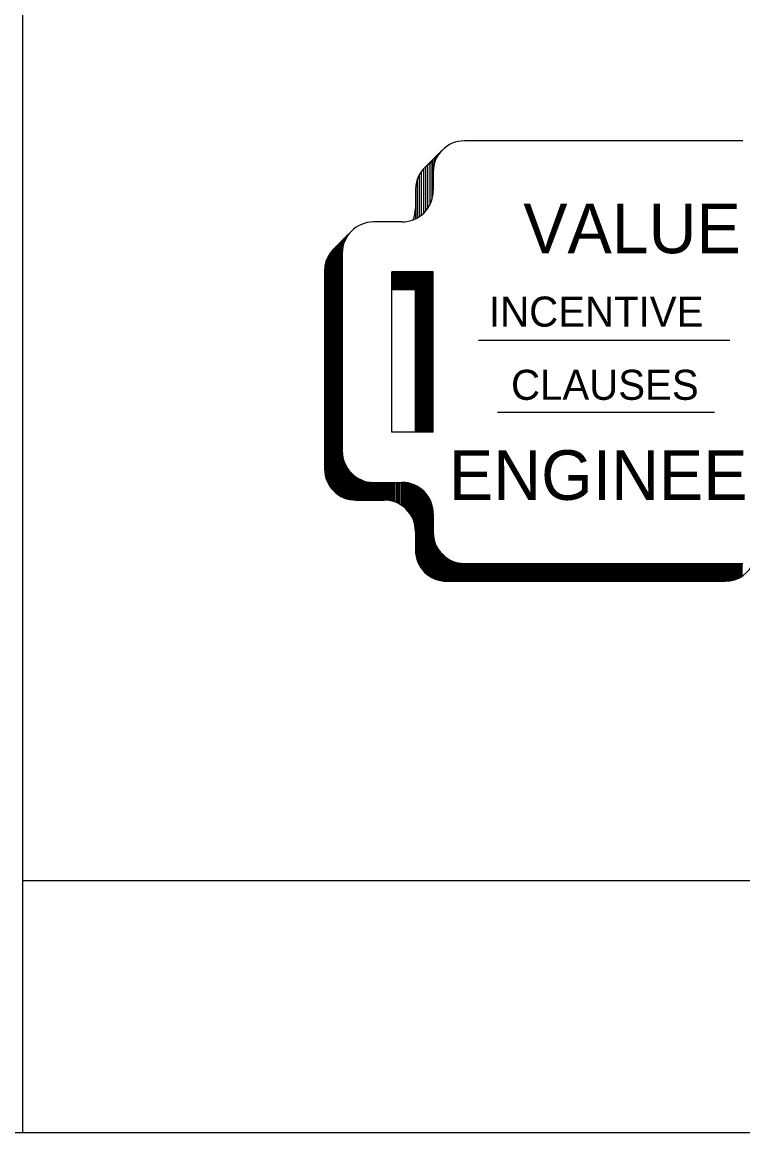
# Model space of a CAD drawing. Extents: x 44743.44 to 44747.1, y 44738.46 to 44741.29.
# Drawn here: x 44743.563 to 44743.6828, y 44738.4578 to 44738.6426 of the extents above; entities that cross this region are included whole.
import ezdxf

# ---------------------------------------------------------------- set-up
doc = ezdxf.new("R2010")
doc.units = 0
for name, color, linetype in [('Level 1', 7, 'Continuous'), ('Level 10', 7, 'Continuous'), ('Level 2', 7, 'Continuous'), ('Level 7', 7, 'Continuous'), ('Level 9', 7, 'Continuous')]:
    doc.layers.add(name, color=color, linetype=linetype)

msp = doc.modelspace()

# ---------------------------------------------------------------- linework, layer by layer
at = {"layer": 'Level 1'}
msp.add_lwpolyline([(44743.43805, 44741.29183), (44747.10474, 44741.29183), (44747.10474, 44738.45783), (44743.43805, 44738.45783)], close=True, dxfattribs=at)
at = {"layer": 'Level 10'}
msp.add_line((44743.56305, 44738.45783), (44743.56305, 44738.49983), dxfattribs=at)
at = {"layer": 'Level 2'}
for p, q in [((44743.62991, 44738.6184), (44743.63286, 44738.62135)), ((44743.63212, 44738.6204), (44743.63212, 44738.62061)), ((44743.63234, 44738.62073), (44743.63234, 44738.62083)), ((44743.6304, 44738.61889), (44743.6304, 44738.61161)), ((44743.63077, 44738.61927), (44743.63077, 44738.61223)), ((44743.63113, 44738.61962), (44743.63113, 44738.61313)), ((44743.63134, 44738.61766), (44743.63134, 44738.61983)), ((44743.63159, 44738.61926), (44743.63159, 44738.62008)), ((44743.63186, 44738.61993), (44743.63186, 44738.62035)), ((44743.62902, 44738.6172), (44743.62902, 44738.61026)), ((44743.62935, 44738.61772), (44743.62935, 44738.6105)), ((44743.6297, 44738.61817), (44743.6297, 44738.6108)), ((44743.63005, 44738.61854), (44743.63005, 44738.61115)), ((44743.62867, 44738.6164), (44743.62867, 44738.61005)), ((44743.62839, 44738.61471), (44743.62839, 44738.6099)), ((44743.61479, 44738.60491), (44743.61773, 44738.60786)), ((44743.61573, 44738.60586), (44743.61573, 44738.56388)), ((44743.61587, 44738.606), (44743.61587, 44738.5638)), ((44743.616, 44738.60613), (44743.616, 44738.56372)), ((44743.6161, 44738.60622), (44743.6161, 44738.56367)), ((44743.61621, 44738.60417), (44743.61621, 44738.60634)), ((44743.61633, 44738.60526), (44743.61633, 44738.60645)), ((44743.61647, 44738.6058), (44743.61647, 44738.6066)), ((44743.61659, 44738.60611), (44743.61659, 44738.60671)), ((44743.61669, 44738.60635), (44743.61669, 44738.60682)), ((44743.61679, 44738.60655), (44743.61679, 44738.60691)), ((44743.61689, 44738.60675), (44743.61689, 44738.60702)), ((44743.61699, 44738.60691), (44743.61699, 44738.60712)), ((44743.6171, 44738.60708), (44743.6171, 44738.60722)), ((44743.6172, 44738.60722), (44743.6172, 44738.60733)), ((44743.61404, 44738.60395), (44743.61404, 44738.56558)), ((44743.6142, 44738.6042), (44743.6142, 44738.56533)), ((44743.61438, 44738.60444), (44743.61438, 44738.56509)), ((44743.61452, 44738.60462), (44743.61452, 44738.56491)), ((44743.61466, 44738.60478), (44743.61466, 44738.56476)), ((44743.61481, 44738.60492), (44743.61481, 44738.56461)), ((44743.61498, 44738.60511), (44743.61498, 44738.56444)), ((44743.61511, 44738.60523), (44743.61511, 44738.56433)), ((44743.61524, 44738.60537), (44743.61524, 44738.56422)), ((44743.61541, 44738.60554), (44743.61541, 44738.5641)), ((44743.61559, 44738.60571), (44743.61559, 44738.56397)), ((44743.61341, 44738.60244), (44743.61341, 44738.56709)), ((44743.61357, 44738.60297), (44743.61357, 44738.56656)), ((44743.61373, 44738.60338), (44743.61373, 44738.56615)), ((44743.61387, 44738.60366), (44743.61387, 44738.56587)), ((44743.61326, 44738.60122), (44743.61326, 44738.56831)), ((44743.63134, 44738.60091), (44743.62444, 44738.60091)), ((44743.63134, 44738.60078), (44743.62444, 44738.60078)), ((44743.63134, 44738.60062), (44743.62444, 44738.60062)), ((44743.63134, 44738.60046), (44743.62444, 44738.60046)), ((44743.63134, 44738.6003), (44743.62444, 44738.6003)), ((44743.63134, 44738.60105), (44743.62839, 44738.5981)), ((44743.63134, 44738.60014), (44743.62444, 44738.60014)), ((44743.63134, 44738.59998), (44743.62444, 44738.59998)), ((44743.63134, 44738.59982), (44743.62444, 44738.59982)), ((44743.63134, 44738.59967), (44743.62444, 44738.59967)), ((44743.63134, 44738.59952), (44743.62444, 44738.59952)), ((44743.63134, 44738.59936), (44743.62444, 44738.59936)), ((44743.63134, 44738.59921), (44743.62444, 44738.59921)), ((44743.63134, 44738.59907), (44743.62444, 44738.59907)), ((44743.63134, 44738.59894), (44743.62444, 44738.59894)), ((44743.63134, 44738.59879), (44743.62444, 44738.59879)), ((44743.63134, 44738.59866), (44743.62444, 44738.59866)), ((44743.63134, 44738.59853), (44743.62444, 44738.59853)), ((44743.63134, 44738.5984), (44743.62444, 44738.5984)), ((44743.63134, 44738.59825), (44743.62444, 44738.59825)), ((44743.62839, 44738.5981), (44743.62444, 44738.5981)), ((44743.62839, 44738.57438), (44743.62839, 44738.5981)), ((44743.62854, 44738.57438), (44743.62854, 44738.59825)), ((44743.62865, 44738.57438), (44743.62865, 44738.59825)), ((44743.62877, 44738.57438), (44743.62877, 44738.59825)), ((44743.62888, 44738.57438), (44743.62888, 44738.59825)), ((44743.62904, 44738.57438), (44743.62904, 44738.59825)), ((44743.62917, 44738.57438), (44743.62917, 44738.59825)), ((44743.62932, 44738.57438), (44743.62932, 44738.59825)), ((44743.62942, 44738.57438), (44743.62942, 44738.59825)), ((44743.62959, 44738.57438), (44743.62959, 44738.59825)), ((44743.62972, 44738.57438), (44743.62972, 44738.59825)), ((44743.62984, 44738.57438), (44743.62984, 44738.59825)), ((44743.62997, 44738.57438), (44743.62997, 44738.59825)), ((44743.63011, 44738.57438), (44743.63011, 44738.59825)), ((44743.63026, 44738.57438), (44743.63026, 44738.59825)), ((44743.63039, 44738.57438), (44743.63039, 44738.59825)), ((44743.63051, 44738.57438), (44743.63051, 44738.59825)), ((44743.63067, 44738.57438), (44743.63067, 44738.59825)), ((44743.63083, 44738.57438), (44743.63083, 44738.59825)), ((44743.63098, 44738.57438), (44743.63098, 44738.59825)), ((44743.63109, 44738.57438), (44743.63109, 44738.59825)), ((44743.63122, 44738.57438), (44743.63122, 44738.59825)), ((44743.61629, 44738.57039), (44743.61629, 44738.56358)), ((44743.61645, 44738.56969), (44743.61645, 44738.56351)), ((44743.61661, 44738.56927), (44743.61661, 44738.56344)), ((44743.61676, 44738.56892), (44743.61676, 44738.56339)), ((44743.61695, 44738.56858), (44743.61695, 44738.56333)), ((44743.61709, 44738.56837), (44743.61709, 44738.56329)), ((44743.61722, 44738.56817), (44743.61722, 44738.56326)), ((44743.6174, 44738.56794), (44743.6174, 44738.56321)), ((44743.61755, 44738.56778), (44743.61755, 44738.56318)), ((44743.6177, 44738.56761), (44743.6177, 44738.56316)), ((44743.61786, 44738.56745), (44743.61786, 44738.56313)), ((44743.61801, 44738.56732), (44743.61801, 44738.56312)), ((44743.61816, 44738.56719), (44743.61816, 44738.56311)), ((44743.61834, 44738.56706), (44743.61834, 44738.5631)), ((44743.61849, 44738.56694), (44743.61849, 44738.5631)), ((44743.61865, 44738.56685), (44743.61865, 44738.5631)), ((44743.61881, 44738.56676), (44743.61881, 44738.5631)), ((44743.61899, 44738.56665), (44743.61899, 44738.5631)), ((44743.61913, 44738.56658), (44743.61913, 44738.5631)), ((44743.61921, 44738.56654), (44743.61921, 44738.5631)), ((44743.61935, 44738.56647), (44743.61935, 44738.5631)), ((44743.61948, 44738.56642), (44743.61948, 44738.5631)), ((44743.61965, 44738.56636), (44743.61965, 44738.5631)), ((44743.61982, 44738.5663), (44743.61982, 44738.5631)), ((44743.61997, 44738.56626), (44743.61997, 44738.5631)), ((44743.62018, 44738.56619), (44743.62018, 44738.5631)), ((44743.62037, 44738.56615), (44743.62037, 44738.5631)), ((44743.62052, 44738.56612), (44743.62052, 44738.5631)), ((44743.62064, 44738.56611), (44743.62064, 44738.5631)), ((44743.6208, 44738.56609), (44743.6208, 44738.5631)), ((44743.62093, 44738.56607), (44743.62093, 44738.5631)), ((44743.62105, 44738.56606), (44743.62105, 44738.5631)), ((44743.62119, 44738.56605), (44743.62119, 44738.5631)), ((44743.62136, 44738.56605), (44743.62136, 44738.5631)), ((44743.62151, 44738.56605), (44743.62151, 44738.5631)), ((44743.62169, 44738.56605), (44743.62169, 44738.5631)), ((44743.62187, 44738.56605), (44743.62187, 44738.5631)), ((44743.62202, 44738.56605), (44743.62202, 44738.5631)), ((44743.62223, 44738.56605), (44743.62223, 44738.5631)), ((44743.62241, 44738.56605), (44743.62241, 44738.5631)), ((44743.62257, 44738.56605), (44743.62257, 44738.5631)), ((44743.62274, 44738.56605), (44743.62274, 44738.5631)), ((44743.62294, 44738.56605), (44743.62294, 44738.5631)), ((44743.62313, 44738.56605), (44743.62313, 44738.5631)), ((44743.62333, 44738.56605), (44743.62333, 44738.5631)), ((44743.62352, 44738.56605), (44743.62352, 44738.5631)), ((44743.62375, 44738.56605), (44743.62375, 44738.56307)), ((44743.62391, 44738.56605), (44743.62391, 44738.56305)), ((44743.62405, 44738.56605), (44743.62405, 44738.56303)), ((44743.62418, 44738.56605), (44743.62418, 44738.56301)), ((44743.6244, 44738.56605), (44743.6244, 44738.56295)), ((44743.62463, 44738.56605), (44743.62463, 44738.56289)), ((44743.62487, 44738.56605), (44743.62487, 44738.56282)), ((44743.6251, 44738.56605), (44743.6251, 44738.56273)), ((44743.6253, 44738.56605), (44743.6253, 44738.56265)), ((44743.62552, 44738.56605), (44743.62552, 44738.56255)), ((44743.6257, 44738.56605), (44743.6257, 44738.56245)), ((44743.62597, 44738.56605), (44743.62597, 44738.56229)), ((44743.62619, 44738.56605), (44743.62619, 44738.56214)), ((44743.62631, 44738.56605), (44743.62631, 44738.56206)), ((44743.6265, 44738.56605), (44743.6265, 44738.5619)), ((44743.62666, 44738.56602), (44743.62666, 44738.56177)), ((44743.62683, 44738.566), (44743.62683, 44738.56161)), ((44743.62698, 44738.56597), (44743.62698, 44738.56145)), ((44743.6271, 44738.56595), (44743.6271, 44738.56133)), ((44743.62727, 44738.56592), (44743.62727, 44738.56111)), ((44743.62745, 44738.56588), (44743.62745, 44738.56087)), ((44743.62764, 44738.56583), (44743.62764, 44738.56058)), ((44743.62782, 44738.56577), (44743.62782, 44738.56027)), ((44743.62797, 44738.56571), (44743.62797, 44738.55993)), ((44743.62814, 44738.56564), (44743.62814, 44738.55948)), ((44743.62832, 44738.56557), (44743.62832, 44738.55876)), ((44743.62845, 44738.56551), (44743.62845, 44738.55402)), ((44743.62862, 44738.56541), (44743.62862, 44738.55329)), ((44743.62879, 44738.56532), (44743.62879, 44738.55283)), ((44743.62894, 44738.56522), (44743.62894, 44738.55248)), ((44743.6291, 44738.56512), (44743.6291, 44738.55219)), ((44743.62925, 44738.56501), (44743.62925, 44738.55194)), ((44743.62943, 44738.56487), (44743.62943, 44738.55169)), ((44743.62957, 44738.56476), (44743.62957, 44738.55152)), ((44743.62972, 44738.56461), (44743.62972, 44738.55134)), ((44743.62986, 44738.56447), (44743.62986, 44738.55119)), ((44743.63002, 44738.5643), (44743.63002, 44738.55103)), ((44743.63018, 44738.56411), (44743.63018, 44738.55089)), ((44743.63036, 44738.56388), (44743.63036, 44738.55073)), ((44743.63052, 44738.56363), (44743.63052, 44738.55061)), ((44743.63066, 44738.56341), (44743.63066, 44738.55052)), ((44743.61847, 44738.5631), (44743.62318, 44738.5631)), ((44743.63079, 44738.56317), (44743.63079, 44738.55043)), ((44743.63089, 44738.56295), (44743.63089, 44738.55037)), ((44743.63102, 44738.56262), (44743.63102, 44738.55029)), ((44743.63114, 44738.56227), (44743.63114, 44738.55022)), ((44743.63123, 44738.56187), (44743.63123, 44738.55017)), ((44743.62839, 44738.55789), (44743.62839, 44738.55482)), ((44743.63135, 44738.55743), (44743.63135, 44738.55012)), ((44743.63149, 44738.5565), (44743.63149, 44738.55006)), ((44743.63163, 44738.55605), (44743.63163, 44738.55)), ((44743.63174, 44738.55575), (44743.63174, 44738.54995)), ((44743.63187, 44738.55547), (44743.63187, 44738.5499)), ((44743.63197, 44738.55528), (44743.63197, 44738.54987)), ((44743.63212, 44738.55503), (44743.63212, 44738.54983)), ((44743.63225, 44738.55482), (44743.63225, 44738.54979)), ((44743.6324, 44738.55461), (44743.6324, 44738.54975)), ((44743.6325, 44738.55448), (44743.6325, 44738.54972)), ((44743.63265, 44738.55431), (44743.63265, 44738.54969)), ((44743.63273, 44738.55421), (44743.63273, 44738.54968)), ((44743.63285, 44738.5541), (44743.63285, 44738.54966)), ((44743.63297, 44738.55397), (44743.63297, 44738.54965)), ((44743.63307, 44738.55389), (44743.63307, 44738.54964)), ((44743.63313, 44738.55384), (44743.63313, 44738.54963)), ((44743.6332, 44738.55378), (44743.6332, 44738.54962)), ((44743.63332, 44738.55368), (44743.63332, 44738.54962)), ((44743.63346, 44738.55357), (44743.63346, 44738.54962)), ((44743.63363, 44738.55345), (44743.63363, 44738.54962)), ((44743.63377, 44738.55336), (44743.63377, 44738.54962)), ((44743.63394, 44738.55326), (44743.63394, 44738.54962)), ((44743.6341, 44738.55317), (44743.6341, 44738.54962)), ((44743.63425, 44738.55309), (44743.63425, 44738.54962)), ((44743.63438, 44738.55303), (44743.63438, 44738.54962)), ((44743.63452, 44738.55296), (44743.63452, 44738.54962)), ((44743.63469, 44738.5529), (44743.63469, 44738.54962)), ((44743.63486, 44738.55284), (44743.63486, 44738.54962)), ((44743.63502, 44738.55279), (44743.63502, 44738.54962)), ((44743.6352, 44738.55273), (44743.6352, 44738.54962)), ((44743.63539, 44738.55268), (44743.63539, 44738.54962)), ((44743.63554, 44738.55265), (44743.63554, 44738.54962)), ((44743.63572, 44738.55262), (44743.63572, 44738.54962)), ((44743.63589, 44738.5526), (44743.63589, 44738.54962)), ((44743.63606, 44738.55258), (44743.63606, 44738.54962)), ((44743.63625, 44738.55257), (44743.63625, 44738.54962)), ((44743.63642, 44738.55256), (44743.63642, 44738.54962)), ((44743.63642, 44738.55248), (44743.67989, 44738.55248)), ((44743.63642, 44738.55243), (44743.67989, 44738.55243)), ((44743.63642, 44738.55238), (44743.67989, 44738.55238)), ((44743.63642, 44738.55231), (44743.67989, 44738.55231)), ((44743.63642, 44738.55222), (44743.67989, 44738.55222)), ((44743.67989, 44738.54961), (44743.67989, 44738.55256)), ((44743.68, 44738.54961), (44743.68, 44738.55256)), ((44743.68009, 44738.54961), (44743.68009, 44738.55256)), ((44743.68017, 44738.54962), (44743.68017, 44738.55256)), ((44743.68031, 44738.54963), (44743.68031, 44738.55256)), ((44743.68041, 44738.54964), (44743.68041, 44738.55256)), ((44743.68054, 44738.54965), (44743.68054, 44738.55256)), ((44743.68064, 44738.54966), (44743.68064, 44738.55256)), ((44743.68075, 44738.54968), (44743.68075, 44738.55256)), ((44743.68085, 44738.5497), (44743.68085, 44738.55256)), ((44743.68097, 44738.54972), (44743.68097, 44738.55256)), ((44743.68109, 44738.54975), (44743.68109, 44738.55256)), ((44743.6812, 44738.54978), (44743.6812, 44738.55256)), ((44743.68135, 44738.54982), (44743.68135, 44738.55256)), ((44743.6815, 44738.54987), (44743.6815, 44738.55256)), ((44743.68163, 44738.54991), (44743.68163, 44738.55256)), ((44743.68175, 44738.54995), (44743.68175, 44738.55256)), ((44743.68189, 44738.55001), (44743.68189, 44738.55256)), ((44743.68202, 44738.55007), (44743.68202, 44738.55256)), ((44743.68214, 44738.55012), (44743.68214, 44738.55256)), ((44743.6823, 44738.5502), (44743.6823, 44738.55256)), ((44743.68245, 44738.55029), (44743.68245, 44738.55256)), ((44743.6826, 44738.55037), (44743.6826, 44738.55256)), ((44743.68274, 44738.55046), (44743.68274, 44738.55256)), ((44743.63642, 44738.55213), (44743.67989, 44738.55213)), ((44743.63642, 44738.55204), (44743.67989, 44738.55204)), ((44743.63642, 44738.55195), (44743.67989, 44738.55195)), ((44743.63642, 44738.55186), (44743.67989, 44738.55186)), ((44743.63642, 44738.55177), (44743.67989, 44738.55177)), ((44743.63642, 44738.55167), (44743.67989, 44738.55167)), ((44743.63642, 44738.55158), (44743.67989, 44738.55158)), ((44743.63642, 44738.55148), (44743.67989, 44738.55148)), ((44743.63642, 44738.5514), (44743.67989, 44738.5514)), ((44743.63642, 44738.55131), (44743.67989, 44738.55131)), ((44743.63642, 44738.55122), (44743.67989, 44738.55122)), ((44743.63642, 44738.55114), (44743.67989, 44738.55114)), ((44743.63642, 44738.55105), (44743.67989, 44738.55105)), ((44743.63642, 44738.55095), (44743.67989, 44738.55095)), ((44743.63642, 44738.55085), (44743.67989, 44738.55085)), ((44743.63642, 44738.55075), (44743.67989, 44738.55075)), ((44743.63642, 44738.55064), (44743.67989, 44738.55064)), ((44743.63642, 44738.55055), (44743.67989, 44738.55055)), ((44743.63642, 44738.55043), (44743.67989, 44738.55043)), ((44743.6336, 44738.54961), (44743.67989, 44738.54961)), ((44743.63642, 44738.55033), (44743.67989, 44738.55033)), ((44743.63642, 44738.55021), (44743.67989, 44738.55021)), ((44743.63642, 44738.5501), (44743.67989, 44738.5501)), ((44743.63642, 44738.54997), (44743.67989, 44738.54997)), ((44743.63642, 44738.54986), (44743.67989, 44738.54986)), ((44743.63642, 44738.54975), (44743.67989, 44738.54975))]:
    msp.add_line(p, q, dxfattribs=at)
for centre, start, end in [((44743.6336, 44738.61471), 111.4079, 180), ((44743.62318, 44738.61164), 338.5921, 0), ((44743.61848, 44738.60122), 111.4079, 180), ((44743.61848, 44738.5683), 180, 270), ((44743.62318, 44738.55789), 0, 90), ((44743.6336, 44738.55481), 180, 270), ((44743.67989, 44738.55481), 270, 338.5921)]:
    msp.add_arc(centre, 0.00521, start, end, dxfattribs=at)
at = {"layer": 'Level 7'}
for p, q in [((44743.68284, 44738.62287), (44743.63655, 44738.62287)), ((44743.63134, 44738.61766), (44743.63134, 44738.61459)), ((44743.62613, 44738.60938), (44743.62142, 44738.60938)), ((44743.61621, 44738.60417), (44743.61621, 44738.57126)), ((44743.63134, 44738.60105), (44743.62444, 44738.60105)), ((44743.62444, 44738.57438), (44743.62444, 44738.60105)), ((44743.63134, 44738.57438), (44743.63134, 44738.60105)), ((44743.63889, 44738.58972), (44743.68071, 44738.58972)), ((44743.64204, 44738.57772), (44743.67813, 44738.57772)), ((44743.63134, 44738.57438), (44743.62444, 44738.57438)), ((44743.62142, 44738.56605), (44743.62613, 44738.56605)), ((44743.63134, 44738.56084), (44743.63134, 44738.55777)), ((44743.63655, 44738.55256), (44743.68284, 44738.55256))]:
    msp.add_line(p, q, dxfattribs=at)
for centre, start, end in [((44743.63655, 44738.61766), 90, 180), ((44743.62613, 44738.61459), 270, 0), ((44743.62142, 44738.60417), 90, 180), ((44743.62142, 44738.57125), 180, 270), ((44743.62613, 44738.56084), 0, 90), ((44743.63655, 44738.55776), 180, 270)]:
    msp.add_arc(centre, 0.00521, start, end, dxfattribs=at)
at = {"layer": 'Level 9'}
for q in [(44743.56305, 44741.24983), (44746.83374, 44738.49983)]:
    msp.add_line((44743.56305, 44738.49983), q, dxfattribs=at)

# ---------------------------------------------------------------- texts
at = {"layer": 'Level 2'}
for s, height, p in [('VALUE', 0.008249, (44743.64633, 44738.60417)), ('INCENTIVE', 0.005, (44743.64062, 44738.59196)), ('CLAUSES', 0.005, (44743.64429, 44738.57978)), ('ENGINEERING', 0.0082494, (44743.63397, 44738.56314))]:
    msp.add_text(s, height=height, dxfattribs=at).set_placement(p)

doc.saveas('drawing.dxf')
